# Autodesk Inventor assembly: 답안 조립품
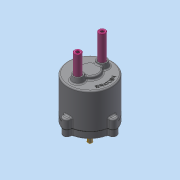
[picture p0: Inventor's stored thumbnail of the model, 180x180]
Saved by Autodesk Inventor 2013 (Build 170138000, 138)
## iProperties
Created: 2020-07
Part Number: 답안 조립품
Document SubType Name: Assembly
Designer: dgall
Author: dgall
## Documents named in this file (14)
- C:\Users\dgall\Desktop\600706V1018\답안 조립품.iam
- C:\Users\dgall\Desktop\600706V1018\본체.ipt
- C:\Users\dgall\Desktop\600706V1018\개스킷.ipt
- C:\Users\dgall\Desktop\600706V1018\볼트 M5.ipt
- C:\Users\dgall\Desktop\600706V1018\오일 실.ipt
- C:\Users\dgall\Desktop\600706V1018\커버.ipt
- C:\Users\dgall\Desktop\600706V1018\멈춤링 22x1.2.ipt
- C:\Users\dgall\Desktop\600706V1018\메인 축.ipt
- C:\Users\dgall\Desktop\600706V1018\베어링 NA 4900.ipt
- C:\Users\dgall\Desktop\600706V1018\판캠.ipt
- C:\Users\dgall\Desktop\600706V1018\멈춤링 10x1.ipt
- C:\Users\dgall\Desktop\600706V1018\가변스프링-1.ipt
- C:\Users\dgall\Desktop\600706V1018\슬라이드 축.ipt
- C:\Users\dgall\Desktop\600706V1018\가변스프링-2.ipt
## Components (3 placed, 3 different names)
1. 개스킷:1
2. 가변스프링-1:1
3. 가변스프링-2:1
